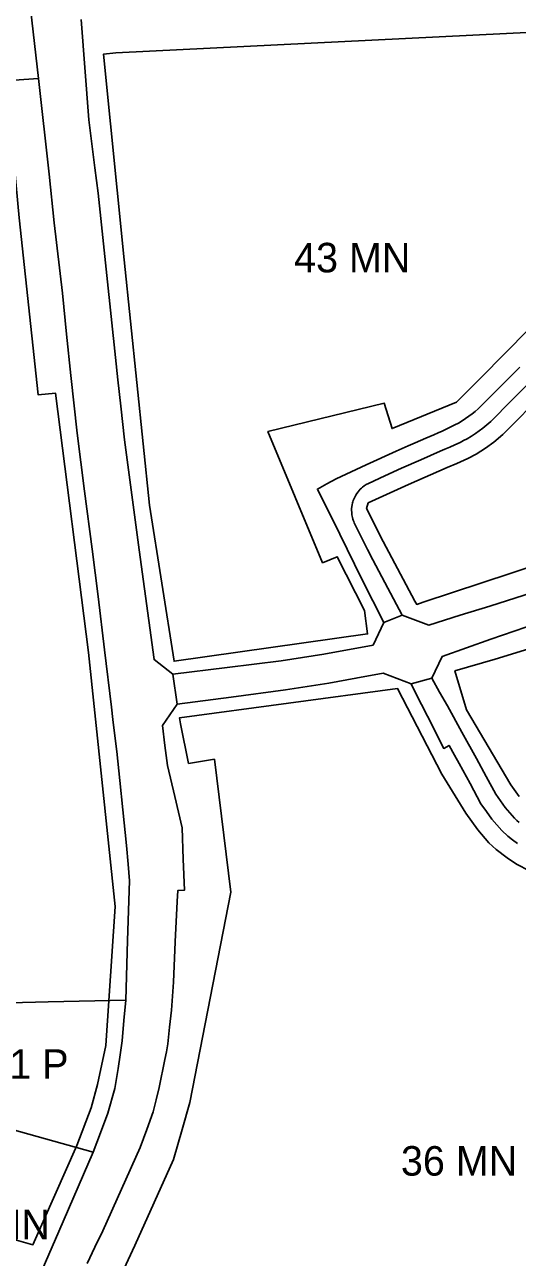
# Model space of a CAD drawing. Extents: x -294445 to -292055, y 21869 to 23693.
# Drawn here: x -293575 to -293408.1, y 23039.5 to 23457 of the extents above; entities that cross this region are included whole.
import ezdxf

# ---------------------------------------------------------------- set-up
doc = ezdxf.new("R2010")
doc.units = 0
for name, color, linetype in [('linie_rozgraniczajace', 7, 'Continuous'), ('linie_zabudowy_nieprzekraczalne', 7, 'Continuous'), ('oznaczenia_przeznaczen', 7, 'Continuous')]:
    doc.layers.add(name, color=color, linetype=linetype)

msp = doc.modelspace()

# ---------------------------------------------------------------- linework, layer by layer
at = {"layer": 'linie_rozgraniczajace'}
for points in [[(-293575.261, 23483.074), (-293573.415, 23466.585), (-293570.3, 23438.751), (-293585.15, 23437.79)], [(-293575.068, 23021.454), (-293563.422, 23048.255), (-293551.776, 23075.056), (-293549.277, 23081.675), (-293546.777, 23088.294), (-293544.438, 23096.711), (-293543.287, 23103.392), (-293542.629, 23108.08), (-293541.97, 23112.769), (-293541.331, 23119.676), (-293540.691, 23126.582), (-293540.096, 23146.779), (-293539.502, 23166.977), (-293539.684, 23169.812), (-293539.866, 23172.647), (-293540.43, 23178.92), (-293541.661, 23191.05), (-293542.694, 23200.958), (-293543.728, 23210.865), (-293544.282, 23215.227), (-293545.1, 23221.675), (-293545.593, 23225.824), (-293547.925, 23245.291), (-293550.079, 23263.318), (-293552.105, 23279.334), (-293554.643, 23299.017), (-293557.18, 23318.7), (-293559.37, 23338.21), (-293560.752, 23352.131), (-293562.134, 23366.053), (-293564.96, 23389.85), (-293566.675, 23406.41), (-293570.3, 23438.751), (-293573.415, 23466.585)], [(-293407.242, 23340.987), (-293414.293, 23333.914), (-293421.345, 23326.84), (-293422.376, 23325.994), (-293423.407, 23325.148), (-293424.501, 23324.373), (-293425.595, 23323.598), (-293426.809, 23322.838), (-293428.024, 23322.078), (-293429.184, 23321.464), (-293430.345, 23320.849), (-293431.921, 23320.089), (-293433.497, 23319.328), (-293434.877, 23318.747), (-293436.328, 23318.135), (-293437.701, 23317.531), (-293439.075, 23316.928), (-293442.685, 23315.344), (-293445.027, 23314.316), (-293449.114, 23312.523), (-293459.272, 23307.876), (-293469.43, 23303.23), (-293472.603, 23301.463), (-293475.776, 23299.695), (-293468.233, 23284.428), (-293460.69, 23269.16), (-293456.983, 23261.825), (-293453.275, 23254.489), (-293456.925, 23246.884), (-293473.612, 23243.813), (-293488.019, 23241.58), (-293506.371, 23239.303), (-293524.73, 23237.025), (-293531.145, 23241.975), (-293536.117, 23279.158), (-293541.089, 23316.341), (-293542.351, 23327.744), (-293543.349, 23336.76), (-293544.151, 23344.244), (-293547.096, 23372.106), (-293550.041, 23399.969), (-293551.17, 23408.49), (-293552.175, 23416.615), (-293553.182, 23424.754), (-293555.839, 23458.757)], [(-293555.839, 23458.757), (-293553.182, 23424.754), (-293552.175, 23416.615), (-293551.17, 23408.49), (-293550.041, 23399.969), (-293547.096, 23372.106), (-293544.151, 23344.244), (-293543.349, 23336.76), (-293542.351, 23327.744), (-293541.089, 23316.341), (-293536.117, 23279.158), (-293531.145, 23241.975), (-293524.73, 23237.025), (-293523.354, 23226.862), (-293528.294, 23219.601), (-293527.447, 23212.846), (-293526.6, 23206.09), (-293524.115, 23195.535), (-293521.63, 23184.98), (-293521.245, 23174.385), (-293520.86, 23163.79), (-293523.02, 23163.74), (-293523.31, 23160.04)], [(-293585.15, 23437.79), (-293570.3, 23438.751), (-293566.675, 23406.41), (-293564.96, 23389.85), (-293562.134, 23366.053), (-293560.752, 23352.131), (-293559.37, 23338.21), (-293557.18, 23318.7), (-293554.643, 23299.017), (-293552.105, 23279.334), (-293550.079, 23263.318), (-293547.925, 23245.291), (-293545.593, 23225.824), (-293545.1, 23221.675), (-293544.282, 23215.227), (-293543.728, 23210.865), (-293542.694, 23200.958), (-293541.661, 23191.05), (-293540.43, 23178.92), (-293539.866, 23172.647), (-293539.684, 23169.812), (-293539.502, 23166.977), (-293540.096, 23146.779), (-293540.691, 23126.582), (-293566.99, 23126.04), (-293606.058, 23124.988)], [(-293475.776, 23299.695), (-293472.603, 23301.463), (-293469.43, 23303.23), (-293459.272, 23307.876), (-293449.114, 23312.523), (-293445.027, 23314.316), (-293442.685, 23315.344), (-293439.075, 23316.928), (-293437.701, 23317.531), (-293436.328, 23318.135), (-293434.877, 23318.747), (-293433.497, 23319.328), (-293431.921, 23320.089), (-293430.345, 23320.849), (-293429.184, 23321.464), (-293428.024, 23322.078), (-293426.809, 23322.838), (-293425.595, 23323.598), (-293424.501, 23324.373), (-293423.407, 23325.148), (-293422.376, 23325.994), (-293421.345, 23326.84), (-293414.293, 23333.914), (-293407.242, 23340.987)], [(-293402.96, 23264.635), (-293417.35, 23260.06), (-293427.379, 23256.939), (-293438.057, 23253.588), (-293447.068, 23256.95), (-293452.954, 23268.075), (-293457.026, 23275.771), (-293458.84, 23279.2), (-293461.065, 23283.745), (-293461.751, 23285.147), (-293463.29, 23288.291), (-293463.489, 23288.746), (-293463.646, 23289.119), (-293463.787, 23289.553), (-293463.937, 23290.043), (-293464.009, 23290.499), (-293464.078, 23290.933), (-293464.137, 23291.362), (-293464.186, 23291.934), (-293464.202, 23292.469), (-293464.187, 23293.064), (-293464.125, 23293.762), (-293464.027, 23294.389), (-293463.894, 23294.99), (-293463.785, 23295.388), (-293463.633, 23295.86), (-293463.369, 23296.535), (-293463.05, 23297.205), (-293462.782, 23297.686), (-293462.487, 23298.152), (-293462.008, 23298.809), (-293461.669, 23299.214), (-293461.272, 23299.64), (-293460.89, 23300.005), (-293460.482, 23300.357), (-293459.971, 23300.749), (-293459.276, 23301.205), (-293458.494, 23301.628), (-293452.92, 23304.18), (-293447.347, 23306.733), (-293440.793, 23309.624), (-293434.239, 23312.515), (-293432.595, 23313.187), (-293430.951, 23313.86), (-293429.212, 23314.668), (-293427.474, 23315.476), (-293426.267, 23316.127), (-293425.061, 23316.777), (-293423.641, 23317.651), (-293422.22, 23318.525), (-293420.989, 23319.411), (-293419.758, 23320.298), (-293417.096, 23322.604), (-293410.012, 23329.71), (-293402.929, 23336.815)], [(-293402.929, 23336.815), (-293410.012, 23329.71), (-293417.096, 23322.604), (-293419.758, 23320.298), (-293420.989, 23319.411), (-293422.22, 23318.525), (-293423.641, 23317.651), (-293425.061, 23316.777), (-293426.267, 23316.127), (-293427.474, 23315.476)], [(-293427.474, 23315.476), (-293429.212, 23314.668), (-293430.951, 23313.86), (-293432.595, 23313.187), (-293434.239, 23312.515), (-293440.793, 23309.624), (-293447.347, 23306.733), (-293452.92, 23304.18), (-293458.494, 23301.628), (-293459.276, 23301.205), (-293459.971, 23300.749), (-293460.482, 23300.357), (-293460.89, 23300.005), (-293461.272, 23299.64), (-293461.669, 23299.214), (-293462.008, 23298.809), (-293462.487, 23298.152), (-293462.782, 23297.686), (-293463.05, 23297.205), (-293463.369, 23296.535), (-293463.633, 23295.86), (-293463.785, 23295.388), (-293463.894, 23294.99), (-293464.027, 23294.389), (-293464.125, 23293.762), (-293464.187, 23293.064), (-293464.202, 23292.469), (-293464.186, 23291.934), (-293464.137, 23291.362), (-293464.078, 23290.933), (-293464.009, 23290.499), (-293463.937, 23290.043), (-293463.787, 23289.553), (-293463.646, 23289.119), (-293463.489, 23288.746), (-293463.29, 23288.291), (-293461.751, 23285.147), (-293461.065, 23283.745), (-293458.84, 23279.2), (-293457.026, 23275.771), (-293452.954, 23268.075), (-293447.068, 23256.95), (-293453.275, 23254.489), (-293456.983, 23261.825), (-293460.69, 23269.16), (-293468.233, 23284.428), (-293475.776, 23299.695)], [(-293524.73, 23237.025), (-293506.371, 23239.303), (-293488.019, 23241.58), (-293473.612, 23243.813), (-293456.925, 23246.884), (-293453.275, 23254.489), (-293447.068, 23256.95), (-293438.057, 23253.588), (-293427.379, 23256.939), (-293417.35, 23260.06), (-293402.96, 23264.635)], [(-293401.279, 23254.271), (-293417.078, 23248.842), (-293425.322, 23245.89), (-293433.565, 23242.938), (-293437.024, 23235.643), (-293444.065, 23233.745), (-293453.526, 23237.342), (-293462.734, 23235.647), (-293471.941, 23233.953), (-293479.288, 23232.814), (-293486.634, 23231.675), (-293504.994, 23229.269), (-293523.354, 23226.862), (-293524.73, 23237.025)], [(-293407.439, 23186.731), (-293408.24, 23187.476), (-293409.04, 23188.22), (-293410.595, 23190.032), (-293412.151, 23191.844), (-293413.741, 23194.089), (-293415.332, 23196.335), (-293418.626, 23202.372), (-293421.864, 23208.431), (-293426.82, 23217.352), (-293431.777, 23226.273), (-293434.4, 23230.958), (-293437.024, 23235.643), (-293433.565, 23242.938), (-293425.322, 23245.89), (-293417.078, 23248.842), (-293401.279, 23254.271)], [(-293553.755, 23037.405), (-293551.136, 23042.939), (-293548.516, 23048.472), (-293542.183, 23062.586), (-293535.85, 23076.7), (-293533.63, 23082.722), (-293531.41, 23088.745), (-293530.401, 23092.846), (-293529.391, 23096.947), (-293527.445, 23106.523), (-293526.962, 23109.13), (-293526.478, 23111.738), (-293525.847, 23117.443), (-293525.216, 23123.147), (-293524.89, 23127.891), (-293524.563, 23132.635), (-293523.937, 23146.337), (-293523.31, 23160.04), (-293523.02, 23163.74), (-293520.86, 23163.79), (-293521.245, 23174.385), (-293521.63, 23184.98), (-293524.115, 23195.535), (-293526.6, 23206.09), (-293527.447, 23212.846), (-293528.294, 23219.601), (-293523.354, 23226.862), (-293504.994, 23229.269), (-293486.634, 23231.675), (-293479.288, 23232.814), (-293471.941, 23233.953), (-293462.734, 23235.647), (-293453.526, 23237.342), (-293444.065, 23233.745), (-293442.541, 23230.73), (-293438.533, 23222.803), (-293433, 23211.86), (-293431.19, 23212.85), (-293429.338, 23209.541), (-293427.765, 23206.731), (-293424.09, 23199.93), (-293420.415, 23193.13), (-293418.559, 23190.533), (-293416.704, 23187.936), (-293415.038, 23185.996), (-293413.373, 23184.056), (-293411.326, 23182.152), (-293409.694, 23180.89), (-293408.061, 23179.627)], [(-293444.065, 23233.745), (-293437.024, 23235.643), (-293434.4, 23230.958), (-293431.777, 23226.273), (-293426.82, 23217.352), (-293421.864, 23208.431), (-293418.626, 23202.372), (-293415.332, 23196.335), (-293413.741, 23194.089), (-293412.151, 23191.844), (-293410.595, 23190.032), (-293409.04, 23188.22), (-293408.24, 23187.476), (-293407.439, 23186.731)], [(-293424.09, 23199.93), (-293427.765, 23206.731), (-293429.338, 23209.541), (-293431.19, 23212.85), (-293433, 23211.86), (-293438.533, 23222.803), (-293442.541, 23230.73), (-293444.065, 23233.745)], [(-293408.061, 23179.627), (-293409.694, 23180.89), (-293411.326, 23182.152), (-293413.373, 23184.056), (-293415.038, 23185.996), (-293416.704, 23187.936), (-293418.559, 23190.533), (-293420.415, 23193.13), (-293424.09, 23199.93)], [(-293523.31, 23160.04), (-293523.937, 23146.337), (-293524.563, 23132.635), (-293524.89, 23127.891), (-293525.216, 23123.147), (-293525.847, 23117.443), (-293526.478, 23111.738), (-293526.962, 23109.13), (-293527.445, 23106.523), (-293529.391, 23096.947), (-293530.401, 23092.846), (-293531.41, 23088.745), (-293533.63, 23082.722), (-293535.85, 23076.7), (-293542.183, 23062.586), (-293548.516, 23048.472), (-293551.136, 23042.939), (-293553.755, 23037.405)]]:
    msp.add_lwpolyline(points, dxfattribs=at)
for points in [[(-293606.058, 23124.988), (-293566.99, 23126.04), (-293540.691, 23126.582), (-293541.331, 23119.676), (-293541.97, 23112.769), (-293542.629, 23108.08), (-293543.287, 23103.392), (-293544.438, 23096.711), (-293546.777, 23088.294), (-293549.277, 23081.675), (-293551.776, 23075.056), (-293589.79, 23085.71), (-293600, 23106.64), (-293603.17, 23113.13), (-293605.62, 23121.18)], [(-293598.18, 23056.18), (-293594.8, 23074.713), (-293589.79, 23085.71), (-293551.776, 23075.056), (-293563.422, 23048.255), (-293575.068, 23021.454), (-293575.727, 23019.979), (-293576.434, 23018.253), (-293578.598, 23011.442), (-293580.762, 23004.631), (-293592.68, 23009.07)]]:
    msp.add_lwpolyline(points, close=True, dxfattribs=at)
at = {"layer": 'linie_zabudowy_nieprzekraczalne'}
for points in [[(-293377.626, 23455.293), (-293380.028, 23415.915), (-293391.219, 23455.055), (-293544.049, 23447.456), (-293548.238, 23447.056), (-293541.27, 23377.389), (-293532.626, 23294.288), (-293524.349, 23241.364), (-293458.796, 23250.626), (-293459.789, 23258.564), (-293469.06, 23276.757), (-293474.026, 23274.772), (-293492.565, 23319.186), (-293453.167, 23328.779), (-293450.519, 23320.179), (-293428.668, 23329.11), (-293420.391, 23337.379), (-293379.776, 23378.546), (-293344.606, 23397.955), (-293337.705, 23451.274), (-293377.626, 23455.293)], [(-293584.701, 23084.284), (-293587.714, 23073.836), (-293581.665, 23046.457), (-293572.15, 23043.741), (-293557.338, 23077.313), (-293552.486, 23090.161), (-293550.3, 23098.027), (-293547.513, 23111.254), (-293544.312, 23158.272), (-293553.385, 23244.347), (-293564.569, 23332.218), (-293570.426, 23331.686), (-293576.805, 23391.629), (-293581.064, 23437.909)], [(-293398.616, 23332.643), (-293413.001, 23318.213), (-293416.033, 23315.586), (-293418.891, 23313.529), (-293422.062, 23311.578), (-293424.783, 23310.11), (-293428.55, 23308.36), (-293431.892, 23306.992), (-293444.887, 23301.26), (-293458.559, 23294.999), (-293459.109, 23293.135), (-293453.505, 23281.947), (-293442.832, 23261.773), (-293442.158, 23260.621), (-293439.936, 23261.41), (-293310.097, 23304.238)], [(-293371.087, 23255.748), (-293415.548, 23242.094), (-293429.207, 23238.126), (-293425.245, 23224.975), (-293425.245, 23224.975), (-293425.245, 23224.975), (-293410.233, 23199.517), (-293410.233, 23199.517), (-293407.416, 23195.54)], [(-293403.972, 23170.393), (-293408.325, 23172.593), (-293411.565, 23174.752), (-293415.212, 23177.573), (-293417.706, 23179.892), (-293421.43, 23184.231), (-293425.515, 23189.947), (-293433.624, 23203.172), (-293433.624, 23203.172), (-293433.624, 23203.172), (-293448.609, 23232.112), (-293448.609, 23232.112), (-293522.455, 23222.262), (-293522.2, 23220.22), (-293519.457, 23206.793), (-293510.7, 23208.2), (-293505.083, 23163.162), (-293505.083, 23163.162), (-293519.039, 23091.927), (-293519.039, 23091.927), (-293519.039, 23091.927), (-293521.64, 23082.79), (-293524.546, 23072.579), (-293537.618, 23043.448), (-293542.873, 23032.347)]]:
    msp.add_lwpolyline(points, dxfattribs=at)

# ---------------------------------------------------------------- texts
at = {"layer": 'oznaczenia_przeznaczen'}
for s, p in [('43 MN', (-293483.685, 23373.116)), ('1 P', (-293580.156, 23099.939)), ('36 MN', (-293447.49, 23067.142)), ('2 MN', (-293598.369, 23045.609))]:
    msp.add_text(s, height=10, dxfattribs=at).set_placement(p)

doc.saveas('drawing.dxf')
